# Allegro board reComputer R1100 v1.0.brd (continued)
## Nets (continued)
VDD18USBPLL: C501.1 FB3.2 U4.62
VDD33_HUB1: C40.1 C41.1 C43.1 C44.1 C45.1 C46.1 C47.1 C500.1 FB1.2 FB2.1 R41.1 R43.1 R44.1 R50.2 R78.1 R79.1 R80.1 R81.1 U4.19 U4.27 U4.33 U4.39 U4.46 U33.8(VCC)
VDD33_HUB2: C59.1 C62.1 C63.1 C64.1 C65.1 C66.1 C67.1 C68.1 C73.1 FB4.2 R51.1 R52.1 R59.1 R60.2 R61.2 R62.2 R63.2 R65.2 R66.2 R67.2 R68.2 U4.40 U5.5 U5.10 U5.15 U5.23 U5.29 U5.36 U6.4(VCC)
VDD33A_HUB1: C48.1 C49.1 C50.1 C51.1 C52.1 C53.1 C54.1 FB2.2 U4.5 U4.10 U4.49 U4.51 U4.54 U4.57 U4.64
VDD_3.3V: C4.1 FB15.2 J17.2 R164.1
VDD_3V3_PCIE: C166.1 C167.1 C168.1 C169.1 J62.2 J62.4 J62.12 J62.14 J62.16 J62.18 J62.70 J62.72 J62.74 OSC1.1 OSC1.4(VDD) R175.1 R176.2
VDD_3V3_SYS: C13.1 C23.1 C24.1 C30.1 C38.1 C42.1 C58.1 C89.1 C90.1 C91.1 C106.1 C107.1 C110.2 C129.2 C163.1 C503.1 C504.1 C508.1 C509.1 D25.1 D27.1 D40.2 FB1.1 FB4.1 FB9.1 FB15.1 FB26.2 FB27.2 J13.1 J13.7 J26.4 L3.2 R38.1 R85.1 R86.1 R88.1 R89.1 R90.1 R102.1 R113.1 R116.1 R124.1 R125.1 R126.1 R127.1 R128.1 R176.1 R532.1 R653.1 R654.1 TP11.1(TP) U3.9(VCC) U12.21(VCC) U17.8 U19.8(VCC) U20.7 U20.8(VCC) U24.7 U24.8(VCC)
VDD_5V_SYS: C10.1 C11.1 C12.1 C17.1 C31.1 C80.1 C81.1 C108.1 C130.1 C131.1 D63.1 J4.77 J4.79 J4.81 J4.83 J4.85 J4.87 L2.2 R33.2 R104.1 R105.1 R652.1 TP10.1(TP) U7.7 U18.5 U23.5
VDD_IN: C7.1 C8.1 C9.1 C20.1 C21.1 C22.1 D2.2(C) J2.2 J2.4 J2.6 R8.1 R16.1 TP1.1(TP) U1.2(VIN) U2.2(VIN)
VDD_LTE_3V3: C111.1 C115.2 C124.1 C125.1 C126.1 C127.1 J15.2 J15.39 J15.41 J15.52 R116.2 TP31.1(TP) U21.3
VDD_RTC: C104.1 C105.1 D27.2(C) D28.2 D29.2(C) TP22.1(TP) U16.8
VDD_UPS: D2.1 J2.1 J2.3 J2.5 Q1.5 Q1.6 Q1.7 Q1.8 Q1.9
BUZZER_EN: R39.1 U12.11
CAM0_C_N: D58.2 J5.140 J24.8
CAM0_C_P: D59.2 J5.142 J24.9
CAM0_D0_N: D53.2 J5.128 J24.2
CAM0_D0_P: D55.2 J5.130 J24.3
CAM0_D1_N: D56.2 J5.134 J24.5
CAM0_D1_P: D57.2 J5.136 J24.6
CAM_GPIO: D64.2 J4.97 J24.17
CH344_RST: J22.2 U12.15
CM4_GPIO16: J4.29 J17.8
CM4_GPIO17: J4.50 J17.7
CM4_GPIO_VREF: C35.2 J4.78 R29.1 R30.1 R31.1 R106.1 R107.1 R177.1 R178.1 TP16.1(TP)
CM4_IIC0_SCL: D60.2 J4.35 J24.20 R177.2
CM4_IIC0_SDA: D54.2 J4.36 J24.21 R178.2
CM4_IIC1_SCL: R27.1 R30.2 U19.6
CM4_IIC1_SDA: R28.1 R31.2 U19.5
CM4_IIC3_SCL: J14.30 J22.4 R24.1 R88.2 U12.19
CM4_IIC3_SDA: J14.32 J22.6 R25.1 R89.2 U12.20
CM4_IIC5_SCL: J2.11 R6.1 R106.2 U16.6 U17.6
CM4_IIC5_SDA: J2.13 R1.2 R107.2 U16.5 U17.5
CM4_IN1: J4.49 J17.3 U20.2
CM4_IN1_LED: J25.7 U20.6
CM4_IN2: J4.26 J17.4 U20.5
CM4_IN2_LED: J25.8 U20.3
CM4_IO_INT: J4.54 R90.2 U12.22
CM4_OUT1: J4.27 J17.5 U24.2
CM4_OUT1_LED: J22.8 U24.6
CM4_OUT2: J4.25 J17.6 U24.5
CM4_OUT2_LED: J22.10 U24.3
CM4_SDIO_CLK: J4.46 R129.1
CM4_SDIO_CMD: D39.2 J4.47 J26.3 R126.2
CM4_SDIO_DATA0: D42.2 J4.45 J26.7 R127.2
CM4_SDIO_DATA1: D43.2 J4.41 J26.8 R128.2
CM4_SDIO_DATA2: D37.2 J4.24 J26.1 R124.2
CM4_SDIO_DATA3: D38.2 J4.48 J26.2 R125.2
CM4_SPI0_CE0: J4.39 J13.9
CM4_SPI0_CE1: J4.37 J14.51
CM4_SPI0_MISO: J4.40 J13.11 J14.47
CM4_SPI0_MOSI: J4.44 J13.12 J14.49
CM4_SPI0_SCLK: J4.38 J13.10 R111.1
CM4_TPM_IRQ: J4.34 J13.2
CM4_UART0_RXD: J4.51 R100.2
CM4_UART0_TXD: D26.2(C) J4.55 R99.2
CM4_UPS_DET: J2.12 J4.30 R654.2
DO_VDD: J20.7 R163.2 R164.2
EECLK: U4.23 U33.2
EECS: R573.1 U4.24 U33.1
EEDI: U4.26 U33.4
EEDO: U4.25 U33.3
EEPROM_WP: R103.2 U12.10
ETHERNET_LED2: J4.17 R155.1
ETHERNET_LED3: J4.15 R160.1
ETHERNET_PAIR0_N: J4.10 T1.3 U29.2 U29.9
ETHERNET_PAIR0_P: J4.12 T1.1 U29.1 U29.10
ETHERNET_PAIR1_N: J4.6 T1.6 U29.5 U29.6(NC4)
ETHERNET_PAIR1_P: J4.4 T1.4 U29.4 U29.7
ETHERNET_PAIR2_N: J4.9 T1.9 U30.2 U30.9
ETHERNET_PAIR2_P: J4.11 T1.7 U30.1 U30.10
ETHERNET_PAIR3_N: J4.5 T1.12(TD4-) U30.5 U30.6(NC4)
ETHERNET_PAIR3_P: J4.3 T1.10 U30.4 U30.7
ETHERNET_RX_N: J10.3 R80.2 U4.53 U11.4 U11.7
ETHERNET_RX_P: J10.6 R81.2 U4.52 U11.5 U11.6(NC4)
ETHERNET_TX_N: J10.1 R78.2 U4.56 U11.1 U11.10
ETHERNET_TX_P: J10.2 R79.2 U4.55 U11.2 U11.9
EXT_IN1: J20.3 J21.7
EXT_IN2: J20.4 J21.9
EXT_OUT1: J20.5 J21.8
EXT_OUT2: J20.6 J21.10
EXT_RS232_1_RX: J21.13 J23.1
EXT_RS232_1_TX: J21.15 J23.2
EXT_RS232_2_RX: J21.14 J23.3
EXT_RS232_2_TX: J21.16 J23.4
EXT_RS485_1_A: J21.1 J23.8
EXT_RS485_1_B: J21.3 J23.7
EXT_RS485_2_A: J21.2 J23.10
EXT_RS485_2_B: J21.4 J23.9
EXT_VCC_9_36V: C1.1 C2.1 D1.2(C) D3.2(C) Q1.1 Q1.2 Q1.3(S3) Q2.2(E) R2.1 R3.1 R4.1
GLOBAL_EN: J4.99 U18.4(Y)
HDMI0_5V: C86.1 C87.1 D20.2 F2.1 J9.18
HDMI0_CEC: J5.151 J9.13 U10.1 U10.10
HDMI0_CLK_N: J5.190 L22.3
HDMI0_CLK_N1: J9.12 L22.4 U9.5 U9.6(NC4)
HDMI0_CLK_P: J5.188 L22.2
HDMI0_CLK_P1: J9.10 L22.1 U9.4 U9.7
HDMI0_HOTPLUG: J5.153 J9.19 U10.2 U10.9
HDMI0_SCL: J5.200 J9.15 U10.5 U10.6(NC4)
HDMI0_SDA: J5.199 J9.16 U10.4 U10.7
HDMI0_TX0_N: J5.184 L21.3
HDMI0_TX0_N1: J9.9 L21.4 U9.2 U9.9
HDMI0_TX0_P: J5.182 L21.2
HDMI0_TX0_P1: J9.7 L21.1 U9.1 U9.10
HDMI0_TX1_N: J5.178 L20.3
HDMI0_TX1_N1: J9.6 L20.4 U8.5 U8.6(NC4)
HDMI0_TX1_P: J5.176 L20.2
HDMI0_TX1_P1: J9.4 L20.1 U8.4 U8.7
HDMI0_TX2_N: J5.172 L19.3
HDMI0_TX2_N1: J9.3 L19.4 U8.2 U8.9
HDMI0_TX2_P: J5.170 L19.2
HDMI0_TX2_P1: J9.1 L19.1 U8.1 U8.10
ISO_5V: R117.1 U22.4
LORA_3V3: C112.2 C113.2 C114.2 C117.1 C118.1 C119.1 J14.2 J14.24 J14.39 J14.41 J14.52 R113.2 TP30.1(TP)
LORAWAN_SX1262_CS: J14.25 U12.1
LORAWAN_SX1262_RST: J14.10 U12.2
LORAWAN_SX1302_RST: R110.2 U12.3
LTE_LED_WWAN#: J15.42 J25.6
LTE_RESET: R109.2 U12.4
NEXTRST: J4.100 R46.1
NLNKA_LED: R83.1 U4.21
NPIBOOT: J4.93 J6.2
NPWR_LED: J4.95 J25.1
NSPD_LED: R84.1 U4.22
PCIE_CLK_N: J5.112 J62.53
PCIE_CLK_NREQ: J5.102 J62.52
PCIE_CLK_P: J5.110 J62.55
PCIE_NRST: J5.109 J62.50
PCIE_RX_N: J5.118 J62.41
PCIE_RX_P: J5.116 J62.43
PCIE_TX_N: J5.124 J62.47
PCIE_TX_P: J5.122 J62.49
PCIE_USIM_PRESE: J15.44 J16.SW R114.2
PL_NLED: J4.21 J25.2
POE_12V: C144.1 C145.1 C146.1 D1.1 TP34.1(TP) U28.1 U28.2
POE_IN_N: C148.2 C149.2 D50.1 D51.2 D52.2 L16.1
POE_IN_N1: C147.1 L16.4 U28.7 U28.8
POE_IN_P: C149.1 D51.1 D52.1 L15.2
POE_IN_P1: C147.2 L16.3 U28.5 U28.6
RS485_POWER_EN: R122.1 U12.14
RTC_INT: C109.1 R104.2 U16.3
RUN_PG: J4.92 R36.2
SD_DET: R87.1 U12.16
SD_VDD_OVERRIDE: J4.73 R26.1
TPM_RST: J13.3 U12.5
TRCT: C88.1 J10.4 J10.5 J10.9 J10.12 R82.2
UART_3V3: C97.1 C100.2 D24.1 R91.1 R96.1 R98.1 TP21.1(TP) U13.2 U15.1(VIO)
USB1_RST: C55.1 R44.2 R46.2 R64.1 U4.12
USB2_RST: C61.1 R52.2 R59.2 R71.2 U5.26 U6.2
USB2_RST_EN: R71.1 U12.13
USB2_VBUS_EN1: R65.1 R75.2 U5.12 U7.1
USB2_VBUS_EN2: R66.1 R74.2 U5.16 U7.4
USB2_VRCURN1: R60.1 U5.13 U7.2
USB2_VRCURN2: R61.1 U5.17 U7.3
USB_0M: U3.7 U4.58
USB_0P: U3.1 U4.59
USB_1M: U3.6 U14.6
USB_1P: U3.2 U14.2
USB_C_DM: R530.2 U14.5
USB_C_DP: R531.2 U14.3
USB_DET: C60.1 R51.2 U5.27
USB_DM: J5.103 U3.5
USB_DP: J5.105 U3.3
USB_HUB1_DM2: J22.3 U4.1
USB_HUB1_DM3: U4.3 U5.30
USB_HUB1_DP2: J22.5 U4.2
USB_HUB1_DP3: U4.4 U5.31
USB_HUB2_DM1: L4.4 U5.1
USB_HUB2_DM2: L5.2 U5.3
USB_HUB2_DM3: J14.36 U5.6
USB_HUB2_DM4: J15.36 U5.8
USB_HUB2_DP1: L4.1 U5.2
USB_HUB2_DP2: L5.3 U5.4
USB_HUB2_DP3: J14.38 U5.7
USB_HUB2_DP4: J15.38 U5.9
USB_OTG_ID: C37.1 J5.101 R34.2 R35.1 U3.10 U14.10
USB_OTG_ID1: J6.5(COM2) R34.1
USB_TO_UART_DM: U14.7 U15.8
USB_TO_UART_DP: U14.1 U15.7
USBA_GND: J8.A4 J8.B4 R72.1 R73.1
USBC_DM: D23.2 J11.A7 J11.B7 R530.1
USBC_DP: D22.2 J11.A6 J11.B6 R531.1
USIM_1V8: C116.2 R112.1 R114.1 TP29.1(TP) U21.2
USIM_CLK: C123.1 D31.2 J15.12 J16.C3
USIM_DATA: C122.1 D30.2 J15.10 J16.C7 R115.2
USIM_GND: J15.4 R108.1
USIM_RST: C128.1 D32.2 J15.14 J16.C2
USIM_VDD: C120.1 C121.1 D33.2 J15.8 J16.C1 R115.1
USR_LED_B: J25.5 U12.8
USR_LED_G: J25.4 U12.7
USR_LED_R: J25.3 U12.6
VETH_DVDDH: C160.1 FB9.2 J18.10 J18.12 R82.1
N17790840: J4.89(WL_NDISABLE) TP14.1(TP)
N17790854: J4.91 TP15.1(TP)
N18106868: J4.19 TP12.1(TP)
N21080778: C135.1 C136.2 J9.20 J9.21 J9.22 J9.23 R130.2 R131.1
N21083178: D29.1 J12.2 TP23.1(TP)
N21084468: C109.2 R105.2 U18.2
N21116206: F1.1 J1.1 R182.1
N21116390: D3.1 D5.2 F1.2
N21149713: J14.14 TP25.1(TP)
N21149734: J14.16 TP26.1(TP)
N21149896: J14.31 TP27.1(TP)
N21149903: J14.33 TP28.1(TP)
N21150017: J14.45 R111.2
N21187983: D8.2(C) R2.2 R5.1
N21187993: Q2.1 R5.2
N21188161: D9.1 Q2.3
N21188625: C1.2 D9.2(C) Q1.4 R3.2 R7.1
N21206327: C103.1 R101.2 U16.1 X3.2
N21206924: C102.2 R101.1 U16.2(X2) X3.1
N21339151: J14.22 R110.1
N21339355: J15.22 R109.1
N21392725: C36.1 J6.6 R32.1 R33.1
N21629438: C3.1 R4.2
N21664516: R37.1 U3.8
N21767500: J4.56 R24.2
N21767503: J4.58 R25.2
N21891930: C56.1 R47.1 R49.1 X1.1
N21894342: C57.1 R49.2 U4.60(XO) X1.3
N22026897: J18.1 T1.24
N22026906: J18.2 T1.22
N22026915: J18.3 T1.21
N22026957: J18.7 T1.15
N22026966: J18.8 T1.13
N22027038: R153.2 R159.1 T1.14
N22027110: R151.2 R157.1 T1.20
N22027117: R154.2 R158.1 T1.17
N22027433: J18.11(YELC) R155.2
N22027462: J18.9 R160.2
N22028382: R152.2 R156.1 T1.23
N22028488: D52.4 R153.1
N22028491: D52.3(~2) R154.1
N22029929: C148.1 D50.2 L15.1 L16.2
N22030276: D51.4 R151.1
N22030277: D51.3(~2) R152.1
N22038029: C154.1 R156.2
N22038032: C154.2 C155.2 C156.2 C157.2 C158.1
N22038068: C155.1 R157.2
N22038120: C156.1 R158.2
N22038172: C157.1 R159.2
N22078660: J18.6 T1.19
N22078676: J18.5 T1.16
N22078685: J18.4 T1.18
N22567639: C153.1 T1.11
N22567644: C152.1 T1.8
N22567654: C151.1 T1.5
N22567659: C150.1 T1.2
N22695835: J14.8 TP24.1(TP)
N22714565: R102.2 R103.1 U17.7(WP)
N23370571: R41.2 U4.11
N23400557: R42.2 U4.63
N23401903: R43.2 U4.41
N23402124: R45.2 U4.50
N23405519: R47.2 U4.61
N23449459: J11.A5 R94.1
N23449477: J11.B5 R95.1
N23449775: C98.1 D24.2(C) D25.2(C) U14.9(VCC)
N23449933: D26.1 R98.2 R99.1 U15.5
N23450082: R100.1 U15.4
N23450096: R97.1 U14.8
N23451512: R53.2 U5.28
N23451530: R54.2 U5.22
N23451550: R55.2 U5.24
N23451563: R56.2 U5.25
N23451623: R57.1 U5.11
N23451671: R58.1 U5.35
N23451839: C69.2 C70.2 U5.34
N23451845: R62.1 U5.19
N23451875: C71.2 C72.2 U5.14
N23451879: R63.1 U5.21
N23451944: R69.2 U5.32(XTALOUT)
N23451981: R67.1 U5.18
N23452007: C75.1 R70.2 U5.33 X2.3
N23452009: R68.1 U5.20
N23452027: C74.1 R69.1 R70.1 X2.1
N23452929: FB6.1 J8.B1(VBUS_B)
N23452966: D18.2 J8.B2 L5.1
N23452985: D19.2 J8.B3 L5.4
N23455465: D12.2 R36.1 SW1.2
N23456906: R64.2 U6.3
N23459666: R50.1 U4.28
N23461225: R48.1 U4.44
N23461314: TP19.1(TP) U4.45
N23463209: J10.10 R83.2
N23463212: J10.11(YELC) R84.2
N23463479: TP18.1(TP) U4.20
N23466024: R85.2 U12.18
N23466170: R92.1 U12.23
N23466179: R93.1 U12.24
N23473877: B1.1 D13.2(C) R38.2
N23473909: B1.2(-) D13.1 Q3.3
N23473945: Q3.1 R39.2 R40.1
N23500588: J62.68(SUSCLK(32KHZ) (O)(0/3.3V)) OSC1.3
N23502047: J62.54 R175.2
N23529653: J4.80 R27.2
N23529656: J4.82 R28.2
N23611485: R12.1 U1.4
N23611490: C15.1 U1.6
N23612078: C5.1 U1.1
N23612081: C5.2 R9.1
N23613464: D10.2(C) L2.1 R9.2 R11.1 U1.8
N23613978: R8.2 R10.2 U1.3
N23614867: C17.2 R13.2 R14.1 U1.5
N23615765: C16.1 R11.2
N23616333: C18.1 U2.1
N23616335: C18.2 R15.1
N23616337: D11.2(C) L3.1 R15.2 R18.1 U2.8
N23616378: R16.2 R17.2 R181.2 U2.3
N23616505: R19.1 U2.4
N23616509: C30.2 R20.2 R21.1 U2.5
N23616593: C28.1 U2.6
N23616615: C29.1 R18.2
N23711005: D15.2 J8.A2 L4.3
N23711301: D14.2 J8.A3 L4.2
N23763799: G1.2 R182.2 R183.1
N23781625: R651.2 U33.6
N23800931: R13.1 R652.2
N23801005: R20.1 R653.2
N23869571: D63.2(C) F2.2
N23918848: FB26.1 J24.22
N23953873: J4.28 R6.2
N23953904: J4.31 R1.1
N23955153: FB27.1 J25.9
N23982561: C133.1 L11.2 U22.2
N23982687: R119.1 R122.2 U23.4
N23982695: R120.1 U23.3
N23982720: D34.2(C) R118.2 TP33.1(TP)
N24049462: D41.2 J26.5 R129.2
N24050469: D44.2 J26.9 R86.2 R87.2
N234528750: FB5.2 J8.A1

Pads without a net: J4 16 18 20 57 61 62 63 64 67 68 69 70 72 75 76 94 96; J5 104 106 111 115 117 121 123 127 129 133 135 139 141 143 145 146 147 148 149 152 154 157 158 159 160 163 164 165 166 169 171 175 177 181 183 187 189 193 194 195 196; J6 3; J10 7; J13 4 5 6 13; J14 1 3 5 6 7 11 12 13 17 19 20 23 28 42 44 46 48; J15 1 3 5 6 7 11 13 16 17 19 20 23 24 25 28 30 31 32 33 45 46 47 48 49 51; J16 C6; J24 11 12 14 15 18; J62 5 6 7 8 10 11 13 17 19 20 22 23 24 25 26 28 29 30 31 32 34 35 36 37 38 40 42 44 46 48 56 58 67 69; U4 6 7 8 9 13 14 16 17 18 31 35 36 37 42 43 47; U12 12 17; U15 10 11 12 13 14 15 16; U16 7; U18 1; U19 1 2 3 7; U28 4; U33 7

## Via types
v1: diameter 0.406, hole 0.203, TOP to BOTTOM, 1737 vias
v2: diameter 0.457, hole 0.203, TOP to BOTTOM, 4 vias

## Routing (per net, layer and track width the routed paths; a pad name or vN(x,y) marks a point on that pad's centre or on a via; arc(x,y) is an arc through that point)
5V_ISO_OUT: length 42
  TOP w1.016: J23.6 v1(104.78,20.46) v1(104.25,20.46)
  LYR3 w1.016: v1(89.92,24.14) 100.56,24.14 v1(104.25,20.46) v1(104.78,20.46)
  BOTTOM w0.381: 75.11,17.84 75.03,17.77 TP32.1 ; 75.11,15.61 75.49,15.99 R118.1
  BOTTOM w0.508: R163.1 v1(89.92,24.14) v1(88.98,24.14) 82.91,24.14 77.62,18.86 76.13,18.86 75.11,17.84
  BOTTOM w1.016: R117.2 75.11,15.61 ; 75.11,15.61 75.11,17.84 ; 75.11,15.61 C134.1
5V_TYPC: length 3
  TOP w0.254: U15.3 34.92,54.19 34.6,54.52 ; U15.9 v1(39.03,53.69)
  TOP w0.508: C99.2 34.31,55.19 v1(34.37,55.13) 34.39,55.11 34.39,54.73 34.6,54.52
  vias: v1(10.7,35.78) v1(11.15,35.78) v1(28.04,37.91) v1(28.07,37.45) v1(28.53,37.91) v1(28.55,37.45) v1(33.89,22.9) v1(33.89,22.39) v1(34.37,22.9) v1(34.37,22.39) v1(60.07,3.16) v1(60.07,2.7) v1(60.51,2.7) v1(61.01,12.66) v1(61.01,12.23) v1(61.45,12.23) v1(61.8,10.12) v1(62.23,10.12) v1(62.23,9.66)
+1.8V_OUT: length 17.9
  TOP w0.203: v1(56.52,72.12) 56.6,72.21 J4.88 ; v1(56.16,71.87) 56.2,71.91 J4.90
  LYR6 w0.381: v1(70.59,74.19) 70.27,73.88 67.13,73.88 66.83,74.18 62.23,74.18 60.84,72.78 57.18,72.78 v1(56.52,72.12) 56.26,71.87 v1(56.16,71.87)
  BOTTOM w0.381: v1(70.59,74.19) 71.04,74.65 R112.2
+3.3V_OUT: length 51.4
  TOP w0.305: R26.2 C32.1 59.47,79.88 v1(59.44,79.84)
  LYR3 w0.305: v1(59.44,79.84) 58.06,78.46 v1(58.06,74.87) ; v1(58.02,37.88) 57.69,38.21 57.69,46.09 57.05,46.72 57.05,52.29 56.34,53 56.34,68.01 53.72,70.63 53.72,72.55 53.98,72.81 56.9,72.81 57.2,72.5 v1(57.2,72.07)
  BOTTOM w0.254: R181.1 58.1,37.42 58.1,37.8 v1(58.02,37.88)
  BOTTOM w0.305: v1(57.2,72.07) 57.23,72.1 C33.2 57.62,73.29 R29.2 v1(58.06,74.87)
GND: length 921.8
  TOP w0.121: 70.06,73.34 69.8,73.09 ; 63.43,75.07 63.4,75.09 J4.53 ; 90.87,37.22 90.87,37.31 v1(90.86,37.32) ; 9.1,57.05 9.22,56.93
  TOP w0.203: 69.09,74.61 69.43,74.95 69.43,75.36 69.4,75.39 J4.23 ; J4.1 73.8,76.35 73.81,76.36 ; v1(65.05,42.79) 65.1,42.84 66.47,42.84 66.6,42.71 J5.137 66.6,40.91 66.58,40.88 ; U4.30 47.84,35.87 47.86,35.85 ; 64.11,37.87 64.2,37.96 J5.150 ; J5.156 63,38.29 v1(62.84,38.13) ; 69.8,72.02 J4.22 69.8,73.11 70.13,73.44 ; 32.21,70.24 32.1,70.36 U12.9 30.65,70.36 v1(30.38,70.62) ; U4.32 46.84,36.18 47.09,35.93 v1(47.27,35.93) ; J5.144 65.4,37.76 65.41,37.76 ; 68.99,40.52 69,40.54 J5.125 69,42.44 69.09,42.53 69.09,42.58 ; U4.29 48.34,35.83 48.36,35.8 ; 67.82,37.98 67.8,38 J5.132 v1(67.8,39.31) ; J4.71 59.8,75.15 59.84,75.11 ; J4.98 54.6,73.15 v1(54.36,73.39) ; J4.59 62.2,75.23 v1(62.13,75.16) ; v1(72.21,37.86) 72.6,38.25 J5.108 ; 68.99,37.96 69,37.97 J5.126 69,39.72 68.96,39.76 ; 69.9,41.13 69.93,41.13 70.2,41.41 J5.119 70.2,42.7 v1(70.49,42.99) ; 55.73,37.87 55.8,37.94 J5.192 55.8,39.39 55.76,39.43 ; 72.6,74.89 72.6,74.9 J4.7 ; J4.43 65.4,75.35 v1(65.76,74.99) ; v1(57.18,42.63) 57,42.46 J5.185 57,41.3 57,41.3 57,41.22 ; 59.49,41.22 59.4,41.31 J5.173 59.4,42.7 59.39,42.71 ; 59.49,41.22 60.66,41.22 ; 59.49,41.22 58.24,41.22 v1(58.2,41.25) ; 58.22,42.71 58.2,42.69 J5.179 v1(58.2,41.25) ; J4.65 61,75.17 v1(61.01,75.16) ; v1(66.6,37.35) J5.138 66.6,39.58 ; C49.2 55.47,25.34 R42.1 ; 54.59,37.98 54.6,38 J5.198 54.6,39.37 54.69,39.46 ; v1(59.44,72.1) 59.4,72.13 J4.74 ; J4.33 67.4,75.41 67.41,75.4 v1(67.41,75.2) ; 47.09,35.32 46.93,35.48 U4.34 45.53,35.48 45.38,35.33 45.38,35 45.39,34.99 ; J5.107 v1(72.6,42.57) ; U3.4 v1(60.28,31.13) ; 37.44,64.32 37.49,64.28 C508.2 37.82,63.71 37.82,63.72 ; J4.66 61,72.14 v1(60.99,72.12) ; J5.174 v1(59.4,38.15) ; J4.60 62.2,73.27 v1(62.18,73.29) ; 60.66,41.22 60.6,41.27 J5.167 60.6,42.53 ; 60.66,41.22 v1(61.83,41.22) ; J4.13 71.4,78.63 MH6.1 ; 70.21,39.52 70.2,39.52 J5.120 70.2,38.25 70.08,38.13 ; 71.38,73.44 71.4,73.42 J4.14 71.4,71.92 71.38,71.89 ; 58.37,25.79 58.04,25.46 C48.2 ; 60.68,38.13 60.6,38.21 J5.168 ; J4.2 73.8,72.11 ; 63,42.38 J5.155 63,41.33 62.89,41.22 v1(61.83,41.22) ; C102.1 8.89,70.24 v1(8.91,70.22) ; v1(61.83,41.22) 61.8,41.24 J5.161 61.8,42.57 v1(61.8,42.57) ; 55.73,41.22 54.67,41.22 54.59,41.3 54.6,41.32 J5.197 54.6,42.54 54.51,42.63 ; 55.73,41.22 57,41.22 ; 55.73,41.22 55.8,41.29 J5.191 55.8,42.59 55.73,42.66 ; v1(58.2,41.25) 58.17,41.22 57,41.22 ; v1(58.2,41.25) J5.180 ; J4.32 67.8,73.5 ; J5.162 61.8,38.1 v1(61.7,38) ; 67.8,41.13 67.8,41.14 J5.131 67.8,42.52 67.67,42.66 ; 72.37,73.42 72.6,73.18 J4.8 72.6,72.05 72.6,72.05 ; J5.113 v1(71.4,42.55) ; X1.2 52.18,25.59 v1(52.17,25.59) ; J4.52 63.8,73.22 63.6,73.42 ; 65.97,73.52 65.8,73.36 J4.42 ; J5.186 v1(57,37.82) ; v1(71.4,37.85) J5.114
  TOP w0.254: v1(46.41,25.26) 46.5,25.17 R45.1 ; R48.2 v1(44.34,31.01) ; 66.49,15.57 v1(66.7,15.79) v1(66.7,15.25) ; 66.49,15.57 66.29,15.38 ; 66.49,15.57 65.6,15.57 J22.1 ; v1(36.88,53.96) 36.89,53.97 U15.17 36.64,54.69 U15.2 ; C55.2 57.51,34.48 57.76,34.22 v1(57.76,33.92) ; C57.2 v1(52.17,25.59) C50.2 ; v1(43.89,34.86) 43.89,34.96 43.64,35.22 C43.2 ; C56.2 v1(53.67,25.21) ; 32.11,54.39 32,54.28 31.45,54.28 31.31,54.14 30.61,54.14 ; C54.2 v1(57.27,30.93) ; v1(44.78,34.81) C41.2 ; C51.2 v1(57.28,32.67) ; 35.26,57.42 35.31,57.36 C100.1 35.66,56.87 v1(35.66,56.88) ; C103.2 7.21,69.82 v1(7.22,69.81) ; D23.1 60.45,9.67 v1(60.12,9.99) ; 36.07,56.95 36.14,56.87 ; C101.1 v1(36.66,50.59) ; C46.2 44.34,33.37 v1(44.22,33.49) 44.34,33.6 C14.2
  TOP w0.305: U10.8 U10.3 v1(102.06,49.08) ; v1(101.21,74.53) C59.2 R57.2 ; v1(102.49,71.03) 102.95,71.03 103.29,70.69 R74.1 ; C112.1 70.18,36.44 v1(69.9,36.71) ; v1(46.41,25.26) 46.21,25.45 C53.2 ; 16.15,54.98 16.61,54.98 16.66,55.03 ; 16.15,54.98 D37.1 ; 16.15,54.98 D38.1 16.15,55.48 v1(16.53,55.85) ; C129.1 v1(17.51,51.48) 17.53,51.5 ; D42.1 v1(15.79,61.73) ; R75.1 103.29,71.76 v1(103.18,71.64) ; v1(60.1,12.13) 60.45,11.78 C92.2 60.45,11.08 v1(60.38,11.01) ; C63.2 96.44,64.69 v1(96.37,64.76) 96.3,64.69 R53.1 95.23,64.69 ; 25.89,67.83 25.84,67.87 R93.2 25.84,68.82 ; v1(60.05,13.07) 60.34,13.36 61.69,13.36 61.9,13.14 C93.2 ; 34.67,66.53 34.64,66.56 34.64,67.77 34.53,67.66 34.1,67.66 v1(33.94,67.83) ; v1(16.46,58.74) 16.15,58.43 D39.1 ; 49.05,23.86 U11.3 U11.8 v1(49.05,20.89) ; v1(57,37.82) 57.9,36.92 C19.2 57.73,36.6 57.22,36.09 C47.2 ; C67.2 v1(97.92,74.41) ; 25.84,68.82 25.63,68.82 25.55,68.9 ; 25.84,68.82 R92.2 ; v1(32.34,69.38) 32.54,69.17 32.73,69.17 v1(32.73,69.6) 32.73,69.6 C110.1 ; 8.74,71.94 7.52,71.94 v1(7.04,71.46) ; 35.79,66.51 35.39,66.51 35.36,66.48 ; 36.59,56.85 v1(36.17,56.85) 36.14,56.87 ; v1(25.23,71.38) C91.2 v1(25.99,71.38) C90.2 ; C125.2 78.87,36.03 v1(78.64,36.26) 78.64,35.83 ; C74.2 100.16,64.98 v1(100.21,64.93) ; R37.2 C38.2 60.56,26.05 v1(60.38,25.87)
  TOP w0.375: SW1.4 7.3,13.68 ; SW1.4 4.69,13.68 ; SW1.4 6,14.98 ; 80.36,17.21 R120.2 81.19,17.21 ; U22.1 59.04,24.34 ; U22.1 59.75,23.38 ; U22.1 58.34,23.38 ; 15.65,66.11 D44.1 ; D44.1 16.66,66.11 ; D44.1 16.15,66.61 ; 39.2,73.75 MH1.1 ; MH1.1 42.5,77.06 ; MH1.1 45.81,73.75 ; U16.4 11.54,68.49 ; U16.4 10.51,69.04 ; U16.4 10.51,67.94 ; 109.69,25.85 J1.2 ; J1.2 111.3,27.46 ; J1.2 112.91,25.85 ; J1.2 111.3,24.25 ; 9.75,40.33 U28.3 ; U28.3 12.27,40.33 ; U28.3 11.01,41.58 ; U28.3 11.01,39.07 ; J22.7 65.41,23.76 ; J22.7 65.41,22.23 ; J22.7 66.62,23 ; MH6.1 74.4,79.17 ; MH6.1 71.94,76.71 ; MH6.1 71.94,81.62 ; MH6.1 69.49,79.17 ; 38.18,71.63 U19.4 37.57,72.01 ; C133.2 75.99,17.47 ; C133.2 75.29,18.17 ; C133.2 74.6,17.47 ; MH2.1 45.81,40.75 ; MH2.1 42.5,44.06 ; MH2.1 39.2,40.75 ; MH2.1 42.5,37.45 ; U13.1 61.8,6.45 ; U13.1 61.04,5.62 ; U13.1 61.8,4.8 ; 78.56,24.48 C131.2 78.98,24.09 ; R183.2 112.58,36.15 ; R183.2 112.58,33.94 ; R183.2 111.47,35.05 ; R183.2 113.68,35.05 ; 11.22,74.91 D28.1 ; D28.1 11.22,75.92 ; D28.1 10.72,75.41 ; 110.87,49.41 R130.1 ; R130.1 111.83,50.48 ; R130.1 110.87,51.55 ; C2.2 100.38,34.33 ; C2.2 99.32,35.28 ; C2.2 98.25,34.33 ; 24.48,68.64 C89.2 23.98,69.15 ; 59.38,80.39 C32.2 59.79,80.78 ; 102.88,72.01 R75.1 103.71,72.01 ; 61.28,27.23 C204.2 61.67,27.65 ; J26.13 14.95,49.87 ; J26.13 13.99,48.72 ; J26.13 13.04,49.87 ; J26.13 13.99,51.03 ; J26.11 4.39,65.63 ; J26.11 4.39,63.72 ; J26.11 5.75,64.67 ; J26.11 3.04,64.67 ; 44.34,29.14 C45.2 43.95,29.56 ; 102.12,65.56 C75.2 102.63,65.05 ; 104.04,76.71 MH10.1 106.5,79.17 ; 101.97,63.69 X2.2 ; X2.2 103.54,63.69 ; X2.2 102.76,64.61 ; X2.2 102.76,62.78 ; 19.65,3.09 J25.10 19.65,4.8 ; 53.56,22.38 X1.4 54.48,23.16 ; J26.12 4.39,49.93 ; J26.12 3.04,48.97 ; J26.12 4.39,48.02 ; J26.12 5.75,48.97 ; 43.08,24.36 C501.2 ; C501.2 42.67,24.75 ; C501.2 43.49,24.75 ; 101.69,61.39 X2.4 100.91,60.48 ; 12.15,80.54 J12.1 ; J12.1 12.15,82.05 ; J12.1 12.9,81.3 ; 110.32,41.24 J9.2 111.03,41.94 ; 38.18,58.62 U20.4 ; U20.4 38.18,60.4 ; U20.4 38.56,59.51 ; 36.68,58.62 U20.1 ; U20.1 36.68,60.4 ; U20.1 36.3,59.51 ; 93.96,60.69 MH7.1 97.16,57.48 ; v1(50.59,32.23) 53.34,32.23 ; v1(50.59,32.23) 50.59,34.98 ; v1(50.59,32.23) 50.59,29.47 ; v1(50.59,32.23) 47.83,32.23 ; MH4.1 93.81,73.75 ; MH4.1 90.5,77.06 ; MH4.1 87.2,73.75 ; MH4.1 90.5,70.45 ; C502.2 44.84,27.22 ; C502.2 43.83,27.22 ; C502.2 44.33,26.71 ; 94.41,64.69 C64.2 95.23,64.69 ; J6.4 5.03,31.29 ; J6.4 6.04,30.28 ; J6.4 5.03,29.28 ; 33.69,56.02 C99.1 33.69,57.41 ; 80.85,23.04 R119.2 81.25,23.46 ; 16.66,64 D43.1 16.15,64.51 ; J10.8 55.14,18.06 ; J10.8 54.08,16.99 ; J10.8 53.01,18.06 ; J10.8 54.08,19.13 ; 83.04,30.35 D5.1 ; D5.1 81.64,32.64 ; D5.1 83.04,34.93 ; D5.1 84.43,32.64 ; 36.12,71.98 U19.9 36.12,69.77 ; 58.93,32.65 C119.2 59.34,33.05 ; 47.1,23.53 C88.2 47.61,23.03 ; U7.6 110.1,71.77 ; U7.6 111.13,71.22 ; U7.6 109.07,71.22 ; U7.6 110.1,70.66 ; C104.2 11.22,74.89 ; C104.2 10.72,74.38 ; C104.2 11.22,73.88 ; D20.1 99.5,47.59 ; D20.1 98.99,48.09 ; D20.1 98.99,47.08 ; 61.38,6.53 C97.2 61.88,7.03 ; SW1.3 7.3,20.88 ; SW1.3 6,19.57 ; SW1.3 6,22.18 ; SW1.3 4.69,20.88 ; MH3.1 90.5,44.06 ; MH3.1 87.2,40.75 ; MH3.1 90.5,37.45 ; 14.7,74.8 C105.2 15.09,74.39 ; 17.55,52.39 D40.1 17.05,52.9 ; 13.44,60.07 J26.6 15.55,60.07 ; 43.94,34.06 C14.2 44.34,34.47 ; SW1.1 3.55,16.33 ; SW1.1 3.55,13.72 ; SW1.1 4.85,15.03 ; C87.2 98.99,49.43 ; C87.2 99.49,48.92 ; C87.2 98.99,48.42 ; 109.92,48.16 C136.1 ; C136.1 110.87,47.09 ; C136.1 110.87,49.22 ; C136.1 111.83,48.16 ; J26.10 14.95,64.67 ; J26.10 12.84,64.67 ; J26.10 13.89,65.63 ; 15.65,60.22 D41.1 16.66,60.22
  TOP w0.381: v1(101.7,36.92) 101.71,36.91 R7.2 ; v1(60.3,37.05) 59.77,37.05 59.69,36.97 C6.2
  TOP w0.508: J22.1 66.58,15.38 v1(66.7,15.25) ; C99.1 v1(33.02,56.72) ; D22.1 v1(59.97,8) ; R94.2 v1(68.53,8.78) R95.2
  LYR2_GND w0.254: J9.8 106.86,41.74 106.35,41.24 v1(106.25,41.24) ; J9.11 105.13,43.94 105.11,43.95 ; 107.77,43.62 107.88,43.62 108.56,42.94 J9.5 ; J9.17 101.66,43.73 101.78,43.85 ; J9.14 103.39,41.88 v1(102.77,41.26)
  LYR2_GND w0.375: 42.5,70.45 MH1.1 ; MH1.1 45.81,73.75 ; MH1.1 42.5,77.06 ; MH1.1 39.2,73.75 ; SW1.4 7.3,13.68 ; SW1.4 6,14.98 ; SW1.4 4.69,13.68 ; 39.2,40.75 MH2.1 ; MH2.1 45.81,40.75 ; MH2.1 42.5,44.06 ; MH2.1 42.5,37.45 ; MH3.1 90.5,44.06 ; MH3.1 87.2,40.75 ; MH3.1 90.5,37.45 ; MH3.1 93.81,40.75 ; 6,19.57 SW1.3 ; SW1.3 4.69,20.88 ; SW1.3 6,22.18 ; SW1.3 7.3,20.88 ; 109.69,25.85 J1.2 ; J1.2 112.91,25.85 ; J1.2 111.3,24.25 ; J1.2 111.3,27.46 ; 11.01,39.07 U28.3 ; U28.3 12.27,40.33 ; U28.3 9.75,40.33 ; U28.3 11.01,41.58 ; 54.08,16.99 J10.8 ; J10.8 54.08,19.13 ; J10.8 53.01,18.06 ; J10.8 55.14,18.06 ; SW1.1 3.55,16.33 ; SW1.1 4.85,15.03 ; SW1.1 3.55,13.72 ; 12.15,80.54 J12.1 ; J12.1 12.15,82.05 ; J12.1 12.9,81.3 ; J6.4 5.03,31.29 ; J6.4 6.04,30.28 ; J6.4 5.03,29.28 ; MH6.1 71.94,82.37 ; MH6.1 71.94,75.96 ; MH6.1 68.74,79.17 ; MH6.1 75.15,79.17 ; MH4.1 90.5,77.06 ; MH4.1 90.5,70.45 ; MH4.1 87.2,73.75 ; MH4.1 93.81,73.75 ; MH7.1 100.37,60.69 ; MH7.1 93.96,60.69 ; MH7.1 97.16,63.89 ; MH7.1 97.16,57.48 ; 111.47,35.05 R183.2 ; R183.2 112.58,33.94 ; R183.2 113.68,35.05 ; R183.2 112.58,36.15 ; U22.1 59.04,24.34 ; U22.1 59.75,23.38 ; U22.1 58.34,23.38 ; 110.32,41.24 J9.2 111.03,41.94 ; 107.25,79.17 MH10.1 104.04,75.96
  LYR3 w0.508: J6.1 3.24,36.69 v1(4.52,36.69)
  BOTTOM w0.121: v2(70.18,39.43) 70.16,39.46 70.16,39.61 70.14,39.63 U1.7 ; R73.2 116.64,63.99 v1(116.11,64.53) ; R161.1 115.28,15.14 115.29,15.12 ; C60.2 75.73,73.73 75.29,73.29
  BOTTOM w0.203: U14.4 v1(37.46,23.1) ; J14.29 57.24,25.52 57.38,25.39 ; 58.37,25.79 58.25,25.79 58.04,26 J14.27 ; 58.44,33.11 58.44,33.27
  BOTTOM w0.254: 15.44,51.94 J62.73 12.64,51.94 ; v1(52.17,25.59) 52.13,25.64 51.84,25.64 51.64,25.84 J14.43 ; 15.49,51.44 J62.75 12.84,51.44 ; 33.25,68.77 33.25,69.89 32.87,70.27 31.7,70.27 31.24,70.73 ; 69.32,40.27 69.31,40.28 C15.2 68.8,40.3 v1(68.48,40.63) 68.43,40.68 v1(67.92,40.68) ; 67.68,79.43 71.68,79.43 MH6.1 ; R54.1 85.87,73.61 v1(85.58,73.9) 85.28,73.61 R55.1 R56.1 84.52,73.61 v1(84.13,74) 83.86,73.74 C61.2 ; 12.35,69.33 12.46,69.44 J62.3 ; 60.12,81.01 C107.2 ; C98.2 38.26,26.22 v1(38.76,25.72) ; C114.1 42.9,35.04 43.08,34.86 43.33,34.86 43.36,34.84 ; v1(78.64,36.26) 78.64,36.56 R12.2 78.1,37.11 R10.1 ; v1(11.86,70.32) 12.25,69.94 J62.1 ; 15.39,66 14.96,66.44 J62.15 12.39,66.44 12.32,66.51 ; R17.1 56.91,37.91 v1(57,37.82) 56.9,37.72 R19.2 ; 12.63,52.44 J62.71 15.37,52.44
  BOTTOM w0.305: 4.61,46.58 4.6,46.6 ; OSC1.2 v1(22.03,45.48) 24.31,45.48 24.89,46.06 24.67,46.29 24.67,47.19 C168.2 ; D18.1 113.8,61.52 v1(113.82,61.51) ; v1(37.44,36.26) 37.5,36.31 R573.2 ; v1(16.54,40.83) 16.53,40.82 U29.3 U29.8 ; J14.21 60.44,25.93 v1(60.38,25.87) ; D14.1 113.47,60.5 113.92,60.95 ; C70.1 99.32,68.24 99.34,68.26 ; U18.3 v1(15.7,74.04) ; v1(100.18,68.52) 100.13,68.46 R58.2 ; C108.2 18.34,73.51 v1(18.44,73.62) ; U9.3 v1(105.39,47.84) ; 5.39,61.04 J24.4 ; J15.15 98.15,28.41 ; v1(22.51,41.01) 22.49,40.99 U30.3 U30.8 v1(22.49,38.86) ; v1(69.9,36.71) 70.14,36.71 70.44,36.41 J14.4 ; D33.1 93.06,57.86 C120.2 ; D15.1 113.34,58.54 v1(113.34,58.53) ; C28.2 47.13,40.1 v1(47.02,39.99) ; C106.2 v1(15.67,20.28) ; v1(2.44,61.05) 2.45,61.04 ; 113.87,63.16 113.41,62.7 D19.1 ; C40.2 46.02,38.18 v1(45.8,37.96) ; C123.2 93.06,61.92 v1(92.81,61.92) ; J16.G1 v1(86.89,55.97) ; D32.1 91.58,59.16 J16.C5 89.68,59.16 89.59,59.24 ; J15.9 100.55,28.37 ; 110.04,36.99 109.42,36.99 108.69,36.26 R108.2 108.69,35.18 C111.2
  BOTTOM w0.375: 13.98,55.53 J62.57 ; J62.57 12.83,55.94 ; J62.57 15.13,55.94 ; 12.3,54.03 D64.1 ; D64.1 12.3,55.04 ; D64.1 12.8,54.54 ; 93.75,34.06 J15.18 ; J15.18 93.75,36.57 ; J15.18 94.28,35.32 ; J10.8 55.14,18.06 ; J10.8 54.08,19.13 ; J10.8 53.01,18.06 ; J10.8 54.08,16.99 ; D8.1 109.44,30.42 ; D8.1 108.49,31.37 ; D8.1 107.53,30.42 ; D8.1 108.49,29.46 ; 8.9,45.18 C504.2 ; C504.2 9.29,45.59 ; C504.2 9.29,44.77 ; 86.89,66 J16.G2 ; J16.G2 88.04,66.91 ; J16.G2 85.73,66.91 ; J16.G2 86.89,67.81 ; J16.G3 78.09,67.81 ; J16.G3 76.93,66.91 ; J16.G3 79.24,66.91 ; J16.G3 78.09,66 ; 13.27,15.02 J13.8 10.36,15.02 ; C62.2 100.85,71.35 ; C62.2 100.02,71.35 ; C62.2 100.43,70.96 ; MH1.1 45.56,73.75 ; MH1.1 42.5,76.81 ; MH1.1 39.45,73.75 ; 22.84,73.14 R40.2 23.25,72.74 ; 66.49,77.57 U17.4 ; U17.4 67.52,78.13 ; U17.4 67.52,77.02 ; U17.4 68.55,77.57 ; 87.35,36.57 J15.34 87.35,34.06 ; 4.69,13.68 SW1.4 ; SW1.4 6,14.98 ; SW1.4 7.3,13.68 ; MH7.1 100.37,60.69 ; MH7.1 97.16,57.48 ; MH7.1 97.16,63.89 ; MH7.1 93.96,60.69 ; 54.84,25.86 J14.35 54.84,28.37 ; 5.56,63.59 J24.SH3 ; J24.SH3 6.57,63.03 ; J24.SH3 6.57,64.14 ; J24.SH3 7.57,63.59 ; J17.1 71.65,23.02 ; J17.1 69.82,23.79 ; J17.1 67.98,23.02 ; J17.1 69.82,22.26 ; 12.83,61.94 J62.33 15.13,61.94 ; 21.14,45.58 OSC1.2 ; OSC1.2 22.06,46.37 ; OSC1.2 20.23,46.37 ; OSC1.2 21.14,47.16 ; 5.03,29.28 J6.4 ; J6.4 5.03,31.29 ; J6.4 6.04,30.28 ; 12.83,67.94 J62.9 15.13,67.94 ; TP7.1 110.9,30.37 ; TP7.1 110.19,29.67 ; TP7.1 110.19,31.08 ; 19.74,40.42 C152.2 ; C152.2 20.75,40.42 ; C152.2 20.25,40.92 ; 101.38,67.7 C66.2 100.97,68.09 ; 5.56,50.99 J24.SH2 ; J24.SH2 6.57,50.43 ; J24.SH2 7.57,50.99 ; 105.19,27.72 J15.54 ; J15.54 106.6,29.57 ; J15.54 108,27.72 ; 65.51,27.12 J14.15 ; J14.15 66.04,25.86 ; J14.15 66.04,28.37 ; U6.1 80.67,75.77 ; U6.1 79.72,74.91 ; U6.1 81.62,74.91 ; 14.08,40.34 C150.2 ; C150.2 15.09,40.34 ; C150.2 14.58,40.85 ; J24.SH1 9.77,50.99 ; J24.SH1 7.76,50.99 ; J24.SH1 8.77,51.54 ; J24.SH1 8.77,50.43 ; R651.1 28.72,35.02 ; R651.1 28.3,34.63 ; R651.1 29.13,34.63 ; 99.91,69.45 C65.2 ; C65.2 100.31,69.04 ; C65.2 100.31,69.86 ; 9.22,29.98 C37.2 ; C37.2 8.83,30.39 ; C37.2 9.22,30.8 ; 8.79,45.61 C503.2 ; C503.2 8.09,46.31 ; C503.2 8.79,47.01 ; 55.24,36.57 J14.34 55.24,34.06 ; 9.77,56.54 J24.13 7.76,56.54 ; 24.09,40.37 C153.2 ; C153.2 25.1,40.37 ; C153.2 24.59,40.87 ; 111.3,24.25 J1.2 ; J1.2 112.91,25.85 ; J1.2 111.3,27.46 ; 87.45,73.75 MH4.1 ; MH4.1 93.56,73.75 ; MH4.1 90.5,76.81 ; U28.3 11.01,41.58 ; U28.3 12.27,40.33 ; U28.3 11.01,39.07 ; 71.12,24.03 C4.2 ; C4.2 70.71,24.42 ; C4.2 71.54,24.42 ; 78.49,37.1 R12.2 78.1,36.69 ; TP13.1 16.28,75.65 ; TP13.1 14.87,75.65 ; TP13.1 15.57,74.95 ; TP13.1 15.57,76.35 ; 97.82,70.67 C71.1 97.31,71.17 ; 92.81,63.95 D30.1 92.31,63.45 ; 15.13,60.44 J62.39 12.83,60.44 ; 93.27,59.7 C128.2 ; C128.2 93.68,60.1 ; C128.2 92.86,60.1 ; 54.29,73.81 TP17.1 ; TP17.1 54.99,74.52 ; TP17.1 54.99,73.11 ; 100.24,55.21 TP9.1 ; TP9.1 100.94,55.91 ; TP9.1 100.94,54.5 ; TP9.1 101.65,55.21 ; J15.53 77.3,29.57 ; J15.53 77.3,25.86 ; J15.53 78.7,27.72 ; U17.2 67.52,80.67 ; U17.2 67.52,79.56 ; U17.2 68.55,80.11 ; U17.2 66.49,80.11 ; 80.95,34.06 J15.50 80.95,36.57 ; 98.45,68.48 C69.1 97.95,67.97 ; 39.45,40.75 MH2.1 ; MH2.1 45.56,40.75 ; MH2.1 42.5,43.81 ; MH2.1 42.5,37.7 ; 111.03,41.94 J9.2 110.32,41.24 ; 56.7,73.83 C34.1 56.2,74.33 ; 12.83,64.94 J62.21 15.13,64.94 ; 92.31,61.42 D31.1 v1(92.81,61.92) ; 7.57,58.04 J24.10 5.56,58.04 ; 15.13,57.44 J62.51 12.83,57.44 ; 56.73,73.83 C33.1 57.23,74.33 ; TP6.1 41.23,45.78 ; TP6.1 41.23,44.37 ; TP6.1 41.93,45.08 ; 107.25,79.17 MH10.1 104.04,75.96 ; 46.6,27.72 J14.53 43.79,27.72 ; 15.13,63.44 J62.27 12.83,63.44 ; 14.53,74.04 U18.3 15.13,74.45 ; 63.91,47.02 C16.2 64.92,47.02 ; C151.2 18.5,40.85 ; C151.2 19,40.34 ; C151.2 17.99,40.34 ; Q3.2 21.99,73.82 ; Q3.2 21.99,72.3 ; Q3.2 22.81,73.06 ; Q3.2 21.16,73.06 ; U17.1 68.55,81.38 ; U17.1 66.49,81.38 ; U17.1 67.52,80.83 ; U17.1 67.52,81.94 ; 112.58,33.94 R183.2 ; R183.2 111.47,35.05 ; R183.2 112.58,36.15 ; R183.2 113.68,35.05 ; 67.52,78.29 U17.3 ; U17.3 68.55,78.84 ; U17.3 66.49,78.84 ; U17.3 67.52,79.4 ; 94.03,57.67 C121.2 94.45,58.06 ; 9.77,53.54 J24.19 7.76,53.54 ; 76.6,75.52 C68.2 76.21,75.11 ; 9.02,16.27 D12.1 8.51,16.77 ; 12.3,51.96 D54.1 ; D54.1 12.8,52.47 ; D54.1 12.3,52.97 ; 6,19.57 SW1.3 ; SW1.3 6,22.18 ; SW1.3 4.69,20.88 ; SW1.3 7.3,20.88 ; MH6.1 75.15,79.17 ; MH6.1 68.74,79.17 ; MH6.1 71.94,75.96 ; MH6.1 71.94,82.37 ; 84.95,36.57 J15.40 84.95,34.06 ; 12.3,52.98 D60.1 12.3,53.99 ; 3.55,13.72 SW1.1 ; SW1.1 3.55,16.33 ; SW1.1 4.85,15.03 ; 34.52,17.86 C160.2 34.11,17.46 ; J24.SH4 9.77,63.59 ; J24.SH4 7.76,63.59 ; J24.SH4 8.77,64.14 ; R35.2 9.05,31.82 ; R35.2 8.55,31.32 ; R35.2 9.05,30.81 ; 29.11,32.84 U33.5 ; U33.5 30.14,33.4 ; U33.5 31.17,32.84 ; U33.5 30.14,32.29 ; 12.3,63.82 D53.1 v1(12.3,62.63) D55.1 v1(12.3,61.68) D56.1 v1(12.3,60.61) D57.1 v1(12.3,59.56) D58.1 v1(12.3,58.5) D59.1 ; 93.27,57.67 C120.2 92.86,58.06 ; 52.84,36.57 J14.40 52.84,34.06 ; 28.72,35.76 C500.2 ; C500.2 29.13,36.15 ; C500.2 28.3,36.15 ; 71.97,19.85 U24.1 72.86,19.47 ; 72.86,21.73 U24.4 71.97,21.35 ; 86.06,75.42 C73.2 ; C73.2 87.07,75.42 ; C73.2 86.57,75.92 ; 90.55,36.57 J15.26 90.55,34.06 ; 7.57,55.04 J24.16 5.56,55.04 ; 48.84,34.06 J14.50 48.84,36.57 ; 90.5,37.7 MH3.1 ; MH3.1 90.5,43.81 ; MH3.1 93.56,40.75 ; MH3.1 87.45,40.75 ; 73.09,27.72 J14.54 ; J14.54 74.49,25.86 ; J14.54 74.49,29.57 ; 92.86,64.16 C122.2 93.27,63.77 ; 72.6,72.51 U21.1 ; U21.1 72.6,74.03 ; U21.1 73.42,73.27 ; 12.78,71.04 J62.76 15.98,71.04 ; 99.07,71.38 C72.1 98.66,70.99 ; U22.1 59.04,24.34 ; U22.1 58.34,23.38 ; U22.1 59.75,23.38 ; 14.38,49.48 J62.77 12.78,50.34 ; 92.31,59.38 D32.1 92.81,59.89 ; 12.15,80.54 J12.1 ; J12.1 12.15,82.05 ; J12.1 12.9,81.3 ; 35.79,26.22 R97.2 36.18,25.81 ; 54.04,25.86 J14.37 54.04,28.37 ; 24.89,47.02 C168.2 24.48,47.42 ; 12.83,58.94 J62.45 15.13,58.94
  BOTTOM w0.381: v1(71.86,73.62) 72.24,73.62 U21.1 72.21,72.89 C116.1 ; J14.26 58.44,33.27 58.55,33.16 ; v1(47.27,35.93) 47.43,36.09 47.3,36.22 47.3,36.93 R21.2 ; v1(58.93,74.64) 58.88,74.59 C35.1 ; J24.7 10.52,59.54 v1(10.53,59.52) ; 105.39,50.1 U9.8 U9.3 ; 54.71,32.45 55.24,32.98 55.24,34.06 ; J14.18 61.64,36.48 v2(61.83,36.66) ; v1(66.6,37.35) 66.7,37.45 R14.2 ; 108.82,50.58 U8.8 U8.3 108.82,48.32 v1(108.84,48.3) ; 76.08,75.35 76.03,75.31 C115.1 ; C509.2 76.99,20.87 77.52,21.4 ; 75.85,74.66 75.88,74.63 C60.2 ; 7.41,62.9 7.77,62.54 J24.1
  BOTTOM w0.508: J15.37 86.15,28.95 86.62,29.43 ; J15.43 83.75,29.04 83.87,29.17 ; 89.41,29.04 89.35,28.98 J15.29 ; 2.49,51.98 2.55,52.04 3.63,52.04 ; 90.53,29.32 90.15,28.94 J15.27 ; C16.2 64.41,46.45 ; 87.18,29.12 86.95,28.89 J15.35 ; 92.33,29.22 92.55,29.01 J15.21 ; J14.9 68.44,28.83 ; C29.2 v1(42.78,47.85)
  BOTTOM w0.762: 2.26,51.75 2.49,51.98
  BOTTOM w1.016: J15.54 106.6,26.65 105.36,25.41 R166.1
  vias: v1(2.16,64.3) v1(2.14,59.02) v1(2.14,45.27) v1(2.16,44.06) v1(2.39,54.06) v1(2.97,43.22) v1(3.08,67.02) v1(3.36,50.1) v1(3.69,56.5) v1(3.63,47.15) v1(3.81,64.65) v1(3.74,48.96) v1(3.76,44.94) v1(3.89,58.99) v1(4.37,40.86) v1(4.5,37.81) v1(4.55,68.54) v1(4.7,28.84) v1(4.63,26.53) v1(4.85,16.34) v1(5.03,18.93) v1(5.36,67.17) v1(5.51,46.82) v1(5.92,31.58) v1(5.97,29.32) v1(6.02,70.6) v1(6.61,19.57) v1(6.63,15.05) v1(7.6,67.32) v1(7.99,51.75) v1(7.93,12.74) v1(8.26,49.59) v1(8.99,30.82) v1(8.99,29.98) v1(9.04,72.15) v1(9.32,70.6) v1(9.91,50.23) v1(10.09,51.75) v1(10.26,43.88) v1(10.44,7.3) v1(10.49,5.57) v1(10.53,61.63) v1(10.57,34.17) v1(10.7,75.25) v1(10.7,74.41) v1(10.67,33.16) v1(10.8,63.92) v1(10.91,57.34) v1(10.85,31.89) v1(10.98,2.7) v1(11.13,82.84) v1(11.66,49.39) v1(12.09,72.07) v1(12.04,44.82) v1(12.37,5.02) v1(12.4,2.22) v1(12.42,1.36) v1(12.6,71.18) v1(12.55,41.39) v1(12.85,75.12) v1(13.31,26.63) v1(13.44,43.83) v1(13.77,79.44) v1(13.72,6.72) v1(13.79,2.22) v1(13.82,1.36) v1(14.1,45.3) v1(14.15,83.04) v1(14.15,6.29) v1(14.58,75.63) v1(15.19,2.22) v1(15.22,1.36) v1(15.24,20.28) v1(15.5,66.1) v1(15.6,60.21) v1(15.67,77.91) v1(15.78,64.55) v1(15.78,8.62) v1(15.98,9.97) v1(16.16,7.25) v1(16.33,80.23) v1(16.41,26.53) v1(16.69,2.22) v1(16.72,1.36) v1(17.2,83.07) v1(17.58,75.2) v1(17.83,2.22) v1(17.86,1.36) v1(18.54,40.83) v1(18.62,42.25) v1(18.75,2.5) v1(19.15,6.16) v1(19.33,40.45) v1(19.43,60.21) v1(19.46,59.14) v1(19.43,58.71) v1(19.46,57.64) v1(19.46,57.21) v1(19.48,56.14) v1(19.51,5.09) v1(19.46,3.01) v1(19.59,41.74) v1(19.71,26.43) v1(19.79,11.72) v1(20.07,45.58) v1(20.2,40.83) v1(20.63,42.58) v1(20.86,76.59) v1(21.44,11.92) v1(22.1,83.12) v1(22.28,67.88) v1(22.33,69.23) v1(22.46,71.97) v1(22.51,26.73) v1(22.53,80.43) v1(23.32,11.77) v1(23.78,81.7) v1(23.85,69.15) v1(23.93,10.5) v1(24.16,40.88) v1(24.34,68.36) v1(24.59,49.26) v1(24.69,7.84) v1(24.84,83.17) v1(25.1,49.31) v1(25.33,11.44) v1(25.43,80.56) v1(25.53,68.92) v1(25.58,27.06) v1(25.73,63) v1(25.96,79.82) v1(26.19,83.17) v1(26.52,60.51) v1(26.52,26.53) v1(26.88,25.28) v1(27.13,7.07) v1(27.31,80) v1(27.31,29.96) v1(27.41,83.12) v1(27.36,35.6) v1(27.36,33.64) v1(27.33,31.61) v1(27.61,81.83) v1(28.68,60.46) v1(28.81,58.91) v1(28.98,80.78) v1(28.96,35.11) v1(29.43,70.61) v1(29.49,69.71) v1(29.59,80.15) v1(29.67,7.07) v1(30.18,54.55) v1(30.25,63.46) v1(30.23,62.93) v1(30.41,69.71) v1(30.69,58.84) v1(30.66,57.16) v1(30.74,81.72) v1(30.79,54.06) v1(30.97,52.39) v1(31.19,83.15) v1(31.3,32.83) v1(31.5,52.44) v1(31.6,37.02) v1(31.6,35.01) v1(31.75,79.79) v1(31.96,80.91) v1(31.93,62.83) v1(32.21,7.07) v1(32.31,83.12) v1(32.62,34.02) v1(32.54,31.79) v1(32.69,46.6) v1(32.72,46.14) v1(32.95,81.62) v1(33,36.18) v1(33.2,47.03) v1(33.2,46.6) v1(33.17,46.14) v1(33.4,83.12) v1(33.35,62.72) v1(33.51,47.87) v1(33.63,47.03) v1(33.63,46.6) v1(33.86,18.78) v1(34.06,47.03) v1(34.47,80.83) v1(34.7,83.12) v1(34.75,7.07) v1(35.23,26.33) v1(35.61,71.03) v1(35.61,24.68) v1(35.66,81.83) v1(35.84,79.29) v1(35.89,70.67) v1(35.84,23.18) v1(35.99,83.12) v1(36.3,53.96) v1(37.16,83.12) v1(37.42,81.06) v1(37.44,81.9) v1(37.46,56.85) v1(37.47,53.96) v1(37.44,39.03) v1(37.47,12.51) v1(37.52,64.15) v1(37.8,65.14) v1(37.95,40.75) v1(38.38,65.52) v1(38.43,83.12) v1(38.48,23.79) v1(38.71,76.64) v1(38.69,13.93) v1(39.02,64.6) v1(38.99,49.39) v1(39.3,38.67) v1(39.58,65.16) v1(39.65,83.12) v1(39.65,58.97) v1(39.68,37.3) v1(39.8,81.85) v1(39.86,77.74) v1(39.88,50.76) v1(40.36,30.44) v1(40.49,80.76) v1(40.67,83.17) v1(41.25,46.29) v1(41.63,30.16) v1(41.86,46.98) v1(41.89,34.51) v1(41.96,77.66) v1(42.4,29.55) v1(42.65,80.33) v1(42.95,28.69) v1(43.79,29.15) v1(44.3,49.44) v1(44.38,80.3) v1(44.53,46.7) v1(44.53,45.94) v1(44.53,45.15) v1(45.06,50.02) v1(45.32,71.46) v1(45.49,77.38) v1(45.87,3.29) v1(46.23,80.17) v1(46.36,73.19) v1(46.43,7.76) v1(46.54,11.49) v1(46.64,75.75) v1(46.69,20.79) v1(46.71,19.87) v1(46.79,23.51) v1(47.22,77.43) v1(47.58,65.24) v1(47.6,63.84) v1(47.6,62.42) v1(47.65,55.61) v1(48.01,80.38) v1(48.14,82) v1(48.41,32.27) v1(48.39,31.2) v1(48.36,30.26) v1(48.41,7.48) v1(48.52,75.17) v1(48.54,34) v1(48.64,13.58) v1(48.8,40.09) v1(48.9,83.1) v1(48.85,11.21) v1(49.3,30.24) v1(49.35,32.24) v1(49.33,31.18) v1(49.48,55.76) v1(49.48,33.97) v1(49.68,70.04) v1(49.86,77.48) v1(49.91,62.5) v1(50.4,81.93) v1(50.5,65.37) v1(50.5,4.08) v1(50.6,39.97) v1(50.56,31.16) v1(50.54,30.22) v1(50.55,28.76) v1(50.72,33.96) v1(50.7,20.46) v1(50.74,55.69) v1(50.93,70.37) v1(51.31,63.82) v1(51.39,40.17) v1(51.39,39.48) v1(51.44,83.1) v1(51.89,32.24) v1(51.87,31.18) v1(51.84,30.24) v1(51.82,3.14) v1(51.95,81.7) v1(52,7.94) v1(52.1,72.43) v1(52.1,50.58) v1(52.02,33.97) v1(52.31,55.69) v1(52.22,40.14) v1(52.22,39.31) v1(52.3,20.46) v1(52.3,11.06) v1(52.38,62.5) v1(52.4,28.51) v1(52.73,73.14) v1(52.76,65.26) v1(52.81,31.15) v1(52.78,30.21) v1(52.83,32.22) v1(52.96,33.95) v1(53.04,81.8) v1(53.19,39.28) v1(53.16,38.21) v1(53.29,50.61) v1(53.24,13.12) v1(53.34,63.84) v1(53.65,6.74) v1(53.9,55.66) v1(53.98,83.1) v1(54.05,29.65) v1(54.08,20.79) v1(54.28,28.54) v1(54.26,16.27) v1(54.23,15.51) v1(54.61,43.42) v1(54.69,42.73) v1(55.5,43.42) v1(55.48,42.68) v1(55.65,37.98) v1(56.16,74.54) v1(56.14,25.62) v1(56.14,25.16) v1(57.2,44.74) v1(57.15,44.16) v1(57.15,43.42) v1(57.25,74.64) v1(57.46,66.51) v1(58.19,32.12) v1(58.24,50.62) v1(58.24,44.13) v1(58.4,4.38) v1(58.93,4.38) v1(59.16,69.91) v1(59.29,83.1) v1(59.24,66.53) v1(59.22,55.85) v1(59.31,30.52) v1(59.41,37.05) v1(59.44,50.64) v1(59.44,44.11) v1(59.9,25.51) v1(60.05,81.47) v1(60.02,24.04) v1(60.02,23.53) v1(60.02,23.08) v1(60.15,74.97) v1(60.63,44.31) v1(60.81,69.96) v1(60.79,55.85) v1(60.94,25.62) v1(61.14,23.46) v1(61.37,6.49) v1(61.67,82.97) v1(61.75,66.53) v1(61.8,2.3) v1(61.83,7) v1(61.83,2.93) v1(62.05,23.35) v1(62.66,22.11) v1(62.93,24.23) v1(63.32,79.79) v1(63.73,60.84) v1(63.93,58.86) v1(64.24,81.32) v1(64.42,67.53) v1(64.42,37.38) v1(64.47,82.97) v1(64.49,40.73) v1(64.49,40.14) v1(64.47,35.29) v1(64.46,24.23) v1(64.75,21.75) v1(64.87,31.84) v1(64.9,31.1) v1(64.92,64.83) v1(65.33,81.5) v1(65.33,28.08) v1(65.43,27.06) v1(65.81,21.75) v1(66.09,31.05) v1(66.19,31.81) v1(66.5,73.62) v1(66.68,76.49) v1(66.63,39.94) v1(66.96,63.97) v1(67.21,82.99) v1(67.29,81.52) v1(67.31,23.1) v1(67.82,70.29) v1(68.02,23.99) v1(68.15,63.33) v1(68.28,64.48) v1(68.23,19.19) v1(68.56,80.63) v1(68.61,78.02) v1(69.22,77) v1(69.45,74.89) v1(69.62,82.99) v1(70.34,63.33) v1(70.41,21.73) v1(70.67,64.55) v1(70.74,71.69) v1(71.12,69.4) v1(71.27,71.31) v1(71.35,67.45) v1(71.5,21.68) v1(71.68,19.01) v1(71.94,37.15) v1(72.47,29.27) v1(72.6,71.06) v1(72.6,69.25) v1(72.6,67.25) v1(72.6,66.28) v1(72.6,64.55) v1(72.6,63.36) v1(72.75,37.15) v1(72.72,34.63) v1(72.9,83.07) v1(72.95,55.76) v1(72.98,43.95) v1(72.95,37.86) v1(72.93,35.52) v1(73.03,50.02) v1(73.38,60.41) v1(73.41,30.26) v1(73.51,58.38) v1(73.48,43.95) v1(73.43,31.97) v1(73.61,37.91) v1(73.71,36.44) v1(73.81,70.85) v1(73.79,69.23) v1(73.87,49.49) v1(74.4,60.74) v1(75.8,79.16) v1(75.97,81.19) v1(76.2,82.64) v1(76.18,74.61) v1(76.2,43.29) v1(76.2,42.3) v1(76.3,61.78) v1(76.23,33.24) v1(76.38,71.41) v1(76.38,70.5) v1(76.33,25.92) v1(76.33,25.18) v1(76.48,69.2) v1(77.04,58.18) v1(77.29,76.19) v1(77.24,61.05) v1(77.35,57.14) v1(77.5,59.02) v1(78.51,56.27) v1(78.56,45.94) v1(78.62,43.7) v1(78.56,35.47) v1(78.67,41.19) v1(79,70.73) v1(79.3,68.64) v1(79.45,29.12) v1(79.48,27.32) v1(79.61,56.07) v1(79.61,50.23) v1(79.58,23.08) v1(79.56,22.44) v1(79.76,56.86) v1(80.06,82.64) v1(80.11,80.99) v1(80.16,78.55) v1(80.32,46.04) v1(80.24,41.21) v1(80.42,70.37) v1(80.47,43.24) v1(81.33,44) v1(81.41,32.32) v1(81.33,31.28) v1(81.43,30.19) v1(81.54,68.57) v1(81.61,24.22) v1(81.61,21.04) v1(81.61,19.32) v1(81.71,17.41) v1(81.79,45.07) v1(81.89,70.37) v1(82.32,36.74) v1(82.58,46.29) v1(82.63,30.06) v1(82.76,75.83) v1(82.76,36.74) v1(82.93,21.2) v1(82.96,19.34) v1(83.47,30.03) v1(83.44,17.41) v1(83.9,22.72) v1(84,78.17) v1(84.2,81.22) v1(84.38,58.64) v1(84.48,83.12) v1(84.43,63.46) v1(84.43,61.56) v1(84.51,59.93) v1(84.48,30.09) v1(84.53,50.05) v1(84.53,49.34) v1(84.71,32.57) v1(84.69,31.63) v1(84.69,30.9) v1(84.74,33.41) v1(84.84,67.58) v1(84.99,75.86) v1(85.37,65.75) v1(85.6,23.05) v1(86.62,81.24) v1(86.54,28.79) v1(86.79,65.11) v1(87.05,49.77) v1(87.2,75.42) v1(87.4,33.13) v1(87.33,31.28) v1(87.51,76.16) v1(87.46,22.51) v1(87.91,78.65) v1(87.99,28.71) v1(87.97,22.51) v1(88.5,83.12) v1(88.5,49.75) v1(88.55,43.78) v1(89.11,57.92) v1(89.18,61.25) v1(89.16,59.42) v1(89.51,64.1) v1(89.59,62.24) v1(90.02,81.32) v1(91.21,78.68) v1(93.53,63.74) v1(94.24,62.42) v1(94.9,51.19) v1(94.95,57.77) v1(95.3,50.81) v1(95.38,27.55) v1(95.54,66.07) v1(95.61,55.94) v1(95.61,50.38) v1(96.19,57.16) v1(96.75,69.38) v1(96.78,55.94) v1(97.13,70.67) v1(97.16,27.57) v1(97.34,67.75) v1(97.59,31.03) v1(97.59,28.99) v1(97.77,57.29) v1(97.94,33.77) v1(98.35,38.7) v1(98.53,70.75) v1(98.63,69.07) v1(98.76,56.04) v1(99.09,50.05) v1(99.34,38.8) v1(99.42,48.22) v1(99.7,70.12) v1(100.61,49.14) v1(100.82,50.23) v1(100.76,33.84) v1(101.2,60.18) v1(102.06,50.2) v1(102.24,43.83) v1(102.29,33.39) v1(102.47,68.77) v1(102.62,55.28) v1(102.87,66.79) v1(102.97,69.33) v1(103.23,64.71) v1(103.63,63.38) v1(103.71,47.69) v1(103.81,50.56) v1(103.76,43.78) v1(104.85,32.4) v1(105.31,50.99) v1(105.74,74.51) v1(105.95,31.13) v1(106.07,75.7) v1(106.61,74.18) v1(106.68,71.18) v1(106.78,72.63) v1(106.83,50.99) v1(107.04,76.26) v1(107.17,30.62) v1(107.29,70.5) v1(107.75,79.87) v1(107.72,77.61) v1(108.71,51.55) v1(108.79,71.08) v1(108.99,47.15) v1(109.25,80.73) v1(109.27,78.83) v1(109.3,77) v1(109.37,29.43) v1(109.37,28.94) v1(109.76,41.24) v1(109.91,52.08) v1(109.86,29.43) v1(109.86,28.94) v1(109.88,27.47) v1(110.34,51.35) v1(110.37,34.91) v1(110.39,31.63) v1(110.52,23.51) v1(110.8,34.12) v1(110.8,28.13) v1(110.9,58.51) v1(110.98,35.93) v1(111.08,51.95) v1(111.05,32.22) v1(111.15,71.87) v1(111.15,71.39) v1(111.28,30.92) v1(111.25,29.3) v1(111.51,33.51) v1(111.61,42.46) v1(111.61,41.46) v1(111.74,23.41) v1(112.3,51.9) v1(112.22,50.81) v1(112.3,50) v1(112.22,48.81) v1(112.25,47.79) v1(112.3,41.52) v1(112.22,28.89) v1(112.4,28) v1(112.42,42.4) v1(112.45,30.42) v1(112.68,31.94) v1(112.8,33.06) v1(112.83,24.19) v1(113.01,14.06) v1(113.26,14.44) v1(113.77,13.73) v1(113.95,14.64) v1(114.48,70.8) v1(114.48,70.37) v1(114.51,62.83) v1(114.61,57.75) v1(114.53,15.05) v1(114.81,58.94) v1(115.12,70.83) v1(115.12,70.37) v1(115.04,66.94) v1(115.04,66.51) v1(115.42,15.02) v1(115.67,70.78) v1(115.67,70.34) v1(115.75,60.49) v1(115.78,58.2) v1(115.83,66.94) v1(115.83,66.51) v1(115.9,59.04) v1(116.46,66.15) v1(116.54,64.65) v1(116.66,59.45) v1(116.89,66.15) v1(116.97,64.65) v1(116.99,63.21) v1(116.92,58.46) v2(59.62,31.91) v2(61.11,32.45)
GND_DO: length 23.9
  LYR6 w1.016: v1(96.09,21.53) v1(95.48,21.53) 95.48,13.91 94.59,13.02 94.59,9.38 J21.12
  BOTTOM w0.121: v1(96.09,21.53) 96.09,21.78
  BOTTOM w1.016: 95.43,21.78 97.08,21.78 98.33,23.02 J20.8 R166.2
GND_EARTH: length 750.1
  TOP w0.121: v1(8.59,0.42) 9.27,0.42 9.45,0.6 J25.S1
  TOP w0.381: v1(22.41,0.39) 21.44,0.39 20.96,0.88 20.47,0.39 v1(19.87,0.39)
  TOP w0.425: 98.58,81.39 J3.1 100.13,82.95 ; 118.38,51.55 C135.2 118.38,49.41 ; J18.13 39.47,7.21 ; J18.13 38.22,8.47 ; J18.13 38.22,5.96 ; 4.8,1.93 MH12.1 0.43,6.3 ; 114.8,80.67 MH14.1 119.17,76.3 ; 94.63,79.84 J3.2 ; J3.2 94.63,82.95 ; J3.2 96.19,81.39 ; 118.38,49.22 R131.2 118.38,47.09 ; 96.19,76.39 J3.3 94.63,77.95 ; 4.8,71.93 MH11.1 0.43,76.3 ; MH13.1 114.8,10.67 ; MH13.1 114.8,1.93 ; MH13.1 119.17,6.3
  TOP w0.635: 97.77,76.29 97.86,76.19 100.13,76.19 99.62,76.71 99.62,78.65 ; 63.11,0.63 63.1,0.62
  TOP w0.889: 57.61,10.6 57.61,12.11 J10.14 ; J10.13 40.29,10.75 40.29,10.22
  TOP w1.27: 113.39,54.6 111.06,54.6 J8.S4 ; 20.96,0.88 21.16,1.08 21.16,5.9 22.04,6.78 22.04,7.19
  LYR2_GND w0.425: MH13.1 114.8,10.67 ; MH13.1 119.17,6.3 ; MH13.1 114.8,1.93 ; 96.19,76.39 J3.3 94.63,77.95 ; 100.13,82.95 J3.1 98.58,81.39 ; 119.17,76.3 MH14.1 114.8,80.67 ; J18.13 38.22,8.47 ; J18.13 39.47,7.21 ; J18.13 38.22,5.96 ; 4.8,1.93 MH12.1 0.43,6.3 ; 94.63,79.84 J3.2 ; J3.2 96.19,81.39 ; J3.2 94.63,82.95
  LYR2_GND w1.27: 98.28,77.94 100.02,76.19 100.13,76.19
  LYR3 w0.425: J18.13 39.47,7.21 ; J18.13 38.22,8.47 ; J18.13 38.22,5.96 ; J3.2 96.19,81.39 ; J3.2 94.63,79.84 ; J3.2 94.63,82.95 ; MH13.1 114.8,10.67 ; MH13.1 114.8,1.93 ; MH13.1 119.17,6.3 ; 94.63,77.95 J3.3 96.19,76.39 ; 114.8,80.67 MH14.1 119.17,76.3 ; 4.8,1.93 MH12.1 0.43,6.3 ; 98.58,81.39 J3.1 100.13,82.95
  LYR3 w0.508: J10.14 57.79,11.94 57.79,10.6
  LYR3 w1.27: 40.69,10.48 40.69,11.16 J10.13 ; 100.13,76.19 100.13,76.31 98.3,78.14 ; 21.19,3.62 21.19,6.28 J18.14
  LYR4_GND w0.425: J18.13 39.47,7.21 ; J18.13 38.22,8.47 ; J18.13 38.22,5.96 ; 98.58,81.39 J3.1 100.13,82.95 ; 119.17,76.3 MH14.1 114.8,80.67 ; 94.63,79.84 J3.2 ; J3.2 94.63,82.95 ; J3.2 96.19,81.39 ; 94.63,77.95 J3.3 96.19,76.39 ; 0.43,76.3 MH11.1 4.8,71.93 ; MH13.1 114.8,10.67 ; MH13.1 119.17,6.3 ; MH13.1 114.8,1.93 ; 4.8,1.93 MH12.1 0.43,6.3
  LYR4_GND w0.635: 65.97,0.78 J11.S2 J11.S1 ; J11.S4 J11.S3 63.11,0.64 63.2,0.55 ; 57.74,10.71 57.74,11.99 J10.14
  LYR4_GND w1.016: 40.69,10.63 40.69,11.16 J10.13
  LYR4_GND w1.27: 99.11,77.51 100.13,76.49 J3.4 ; 21.31,5.98 22.04,6.71 22.04,7.19 ; 113.62,54.39 113.55,54.46 J8.S4 J8.S1
  LYR5_PWR w0.425: 119.17,76.3 MH14.1 114.8,80.67 ; 4.8,71.93 MH11.1 0.43,76.3 ; J3.2 94.63,82.95 ; J3.2 96.19,81.39 ; J3.2 94.63,79.84 ; 96.19,76.39 J3.3 94.63,77.95 ; 98.58,81.39 J3.1 100.13,82.95 ; 0.43,6.3 MH12.1 4.8,1.93 ; 114.8,1.93 MH13.1 ; MH13.1 119.17,6.3 ; MH13.1 114.8,10.67 ; J18.13 39.47,7.21 ; J18.13 38.22,8.47 ; J18.13 38.22,5.96
  LYR5_PWR w0.635: J11.S1 J11.S2 65.97,0.78 ; J10.14 57.86,11.86 57.86,10.55 ; 63.15,0.57 63.11,0.61 J11.S3 J11.S4
  LYR5_PWR w1.27: J8.S1 J8.S4 113.88,54.46 114.15,54.19 ; 21.24,5.85 22.04,6.66 22.04,7.19 ; 98.43,77.89 100.12,76.19 100.13,76.19 ; J10.13 40.59,11.06 40.59,10.45
  LYR6 w0.425: 119.17,76.3 MH14.1 114.8,80.67 ; MH13.1 114.8,10.67 ; MH13.1 119.17,6.3 ; MH13.1 114.8,1.93 ; 4.8,71.93 MH11.1 0.43,76.3 ; J3.2 94.63,82.95 ; J3.2 94.63,79.84 ; J3.2 96.19,81.39 ; 112.5,67.6 112.73,67.6 ; 38.22,5.96 J18.13 ; J18.13 38.22,8.47 ; J18.13 39.47,7.21 ; 0.43,6.3 MH12.1 4.8,1.93 ; 98.58,81.39 J3.1 100.13,82.95 ; 96.19,76.39 J3.3 94.63,77.95
  LYR6 w0.635: J10.13 40.67,11.13 40.67,10.45 ; J11.S1 J11.S2 65.97,0.78 ; J11.S4 J11.S3 63.11,0.64 63.12,0.62 ; J10.14 57.5,10.84 57.81,10.53
  LYR6 w1.27: 98.73,77.71 100.13,76.31 100.13,76.19 ; 22.04,7.19 22.04,6.53 21.31,5.8 ; 113.31,68.41 112.5,67.6 J8.S3 J8.S2
  LYR6 w2.032: 113.62,54.22 113.37,54.46 J8.S4 J8.S1
  LYR7_GND w0.425: 119.17,6.3 MH13.1 114.8,10.67 ; J18.13 38.22,8.47 ; J18.13 38.22,5.96 ; J18.13 39.47,7.21 ; 94.63,77.95 J3.3 96.19,76.39 ; 0.43,6.3 MH12.1 4.8,1.93 ; 4.8,71.93 MH11.1 0.43,76.3 ; J3.2 96.19,81.39 ; J3.2 94.63,82.95 ; J3.2 94.63,79.84 ; 119.17,76.3 MH14.1 114.8,80.67 ; 100.13,82.95 J3.1 98.58,81.39
  LYR7_GND w0.635: J11.S1 J11.S2 65.97,0.78 ; J11.S4 J11.S3 63.11,0.66 63.07,0.62
  LYR7_GND w0.889: J10.14 57.5,10.46 57.53,10.43
  LYR7_GND w1.27: MH13.1 117.63,3.47 117.63,1.69 ; MH13.1 114.8,4.32 112.3,1.82 ; MH13.1 117.91,9.41 117.91,11.04 ; MH13.1 112.83,8.27 112.83,10.88 ; 98.4,77.86 100.07,76.19 100.13,76.19 ; J8.S1 J8.S4 113.88,54.46 113.97,54.37 ; 22.04,7.19 22.04,6.45 21.29,5.7 ; 40.41,10.2 40.41,10.88 J10.13 ; J8.S2 J8.S3 112.5,67.6 113.36,68.46 ; MH11.1 4.8,76.37 1.5,79.67 ; 1.12,10.12 4.8,6.44 MH12.1
  BOTTOM w0.121: 117.99,42.29 117.99,41.49 v1(117.68,41.19) ; 117.99,47.11 v1(117.81,46.93)
  BOTTOM w0.381: v1(22.41,0.39) 21.52,0.39 20.96,0.95 20.4,0.39 v1(19.87,0.39)
  BOTTOM w0.425: 119.17,76.3 v1(117.34,76.3) 115.23,76.3 ; 94.63,79.84 J3.2 ; J3.2 94.63,82.95 ; J3.2 96.19,81.39 ; 94.63,77.95 J3.3 96.19,76.39 ; J18.13 39.47,7.21 ; J18.13 38.22,8.47 ; J18.13 38.22,5.96 ; 4.8,71.93 MH11.1 0.43,76.3 ; 114.8,10.67 MH13.1 119.17,6.3 ; 112.5,67.6 112.73,67.6 ; 100.13,82.95 J3.1 98.58,81.39
  BOTTOM w0.635: J11.S4 J11.S3 63.11,0.64 63.12,0.62 ; 65.97,0.78 J11.S2 J11.S1 ; 97.87,75.93 99.87,75.93 100.13,76.19 99.7,76.63 99.7,78.22
  BOTTOM w0.889: J10.13 40.62,11.08 40.62,10.38 ; 117.83,10.5 117.83,9.33 MH13.1 ; MH11.1 4.8,76.65 1.53,79.92 ; MH12.1 2.55,6.3 0.74,8.11 ; MH12.1 4.8,4.86 2.36,2.42 ; MH12.1 4.8,6.57 1.55,9.82 ; MH14.1 118.24,79.74 118.24,80.66 ; MH14.1 112.22,78.88 112.22,80.94 ; MH14.1 115.23,76.3 118.54,72.99 ; J10.14 57.61,12.11 57.61,10.48 ; MH13.1 114.8,4.82 117.48,2.15 ; MH13.1 112.68,4.18 112.68,1.74 ; MH13.1 112.07,9.03 112.07,10.48
  BOTTOM w1.27: 113.39,68.49 112.5,67.6 J8.S3 J8.S2 ; 113.62,54.37 111.02,54.37 J8.S4 J8.S1 ; 22.04,7.19 22.04,6.81 21.16,5.93 21.16,1.15 20.96,0.95
  vias: v1(0.46,78.17) v1(0.46,75.63) v1(0.43,73.09) v1(0.51,70.75) v1(0.51,68.21) v1(0.51,65.67) v1(0.49,63.13) v1(0.49,60.59) v1(0.49,58.05) v1(0.46,50.81) v1(0.49,48.73) v1(0.49,46.19) v1(0.49,43.65) v1(0.51,19.93) v1(0.51,17.39) v1(0.51,14.85) v1(0.49,11.65) v1(0.49,9.11) v1(0.49,6.57) v1(0.49,4.03) v1(0.54,55.87) v1(0.59,53.33) v1(1.45,40.63) v1(1.5,27.65) v1(1.5,25.11) v1(1.5,22.57) v1(1.48,21.22) v1(1.68,37.6) v1(2.41,75.43) v1(2.41,5.43) v1(2.6,77.57) v1(2.6,7.57) v1(2.87,31.63) v1(2.95,34.4) v1(3,24.78) v1(3.03,27.47) v1(3.08,26.15) v1(3.05,23.46) v1(3.23,29.4) v1(3.74,0.75) v1(3.93,73.91) v1(3.93,3.91) v1(4.36,78.8) v1(4.36,8.8) v1(6.07,74.1) v1(6.07,4.1) v1(6.43,78.25) v1(6.43,8.25) v1(6.68,0.39) v1(7.34,76.3) v1(7.34,6.3) v1(8.77,22.67) v1(9.2,22.67) v1(9.63,22.67) v1(10.06,22.64) v1(11.76,0.39) v1(14.79,0.39) v1(17.33,0.39) v1(25.2,0.39) v1(27.74,0.39) v1(30.28,0.39) v1(32.82,0.39) v1(35.49,0.39) v1(38.08,0.47) v1(40.62,0.47) v1(43.16,0.47) v1(45.7,0.47) v1(48.49,0.47) v1(51.03,0.47) v1(53.57,0.47) v1(56.11,0.47) v1(58.78,0.47) v1(61.32,0.47) v1(63.86,0.47) v1(66.4,0.47) v1(69.19,0.47) v1(71.73,0.47) v1(74.27,0.47) v1(76.81,0.47) v1(79.23,0.47) v1(81.77,0.47) v1(84.31,0.47) v1(86.85,0.47) v1(89.64,0.47) v1(92.18,0.47) v1(94.72,0.47) v1(95.1,83.15) v1(97.26,0.47) v1(97.64,83.15) v1(99.67,0.47) v1(100.18,83.15) v1(102.21,0.47) v1(103.13,83.12) v1(104.75,0.47) v1(105.26,83.15) v1(107.29,0.47) v1(107.8,83.15) v1(110.09,0.47) v1(110.34,83.15) v1(112.41,75.43) v1(112.41,5.43) v1(112.6,77.57) v1(112.6,7.57) v1(112.63,0.47) v1(112.88,83.15) v1(113.79,10.91) v1(113.93,73.91) v1(113.93,3.91) v1(114.36,78.8) v1(114.36,8.8) v1(114.53,56.22) v1(114.91,55.38) v1(115.12,53.99) v1(115.17,0.47) v1(115.42,83.15) v1(115.9,56.22) v1(116.07,74.1) v1(116.07,4.1) v1(116.18,54.7) v1(116.43,78.25) v1(116.43,8.25) v1(116.84,10.98) v1(117.07,55.23) v1(117.1,53.71) v1(117.34,6.3) v1(117.48,39.64) v1(117.71,49.16) v1(117.71,0.47) v1(117.78,83.04) v1(117.93,44.49) v1(118.04,15.05) v1(118.87,61.05) v1(119,58.13) v1(119,55.59) v1(119,53.89) v1(119,50.51) v1(119,47.97) v1(119,2.96) v1(119.08,81.19) v1(119.08,78.65) v1(119.1,73.62) v1(119.05,71.08) v1(119.03,65.98) v1(119.03,63.44) v1(119.03,45.35) v1(119.03,42.81) v1(119.03,40.02) v1(119.05,37.53) v1(119.05,34.99) v1(119.05,32.19) v1(119.05,29.65) v1(119.03,27.11) v1(119.03,24.57) v1(119.03,21.78) v1(119.03,19.24) v1(119.13,16.78) v1(119.13,13.47) v1(119.13,10.68) v1(119.13,8.14) v1(119.23,76.16) v1(119.23,68.54) v1(119.23,5.55)
